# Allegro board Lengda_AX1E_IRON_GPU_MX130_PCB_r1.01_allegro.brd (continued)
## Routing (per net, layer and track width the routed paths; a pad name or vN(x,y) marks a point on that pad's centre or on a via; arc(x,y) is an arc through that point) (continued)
FRM_CLK: length 4.5
  TOP w0.102: U3.A3 28.11,37.82 28.11,34.02 R640.2
GC6_FB_EN: length 60.6
  TOP w0.102: v1(28.66,31.11) 28.78,31.22 28.78,34.46 28.51,34.73 28.51,36.62 29.28,37.4 U3.B2 ; v1(49.7,10.18) 50.03,9.84 GR8.2
  L3 w0.102: v1(29.3,10.51) 31.12,10.51 32.21,11.6 34.35,11.6 34.53,11.78 38.47,11.78 39.36,10.89 40.74,10.89 41.15,11.3 44.67,11.3 45.8,10.17 49.68,10.17 v1(49.7,10.18)
  L3 w0.127: v1(28.66,31.11) 28.66,30.19 27.13,28.66 27.13,18.27 28.83,16.57 v1(29.16,16.57)
  BOTTOM w0.102: R604.2 R603.1 29.64,30.78 29.31,31.11 v1(28.66,31.11) ; v1(29.16,16.57) 29.48,16.25 29.48,10.69 v1(29.3,10.51) 28.87,10.08 26.49,10.08 26.2,10.37 U44.2
GPIO0_PWM_VID: length 96.9
  TOP w0.102: v1(26.48,31.59) 27.35,32.46 27.36,39.77 27.52,39.93 28.83,39.93 29.18,40.28 29.82,40.28 30.08,40.54 U3.C6
  L3 w0.127: v1(67.02,45.24) 65.98,45.3 61.87,41.2 61.87,35.28 62.74,34.41 62.74,24.31 63.31,23.74 63.31,19.72 62.04,18.45 57.1,18.45 53.57,14.92 50.97,14.92 49.86,16.02 40.36,16.02 39.84,16.54 33.69,16.54 33.17,16.02 28.88,16.02 25.98,18.92 25.98,26.47 25.55,26.9 25.55,31.27 25.87,31.59 v1(26.48,31.59)
  BOTTOM w0.203: R651.1 66.9,45.9 67.02,45.78 v1(67.02,45.24)
GPIO2_GPU_EVENT_FBCLAMP: length 25.4
  TOP w0.102: U3.D6 31.28,41.09 v1(31.28,41.1)
  BOTTOM w0.102: Q36.2 24.58,23.85 24.09,24.34 R645.2 24.68,25.31 24.68,26.64 25.76,27.72 25.76,32.71 26.87,33.83 26.87,41.32 27.7,42.14 28.42,42.14 29.87,40.7 30.87,40.7 v1(31.28,41.1)
GPIO4_PWR_EN: length 108
  TOP w0.102: U3.F9 v1(32.13,42.78)
  L3 w0.102: v1(32.13,42.78) 32.55,42.35 32.55,37.17 31.81,36.43 31.81,34.14 32.55,33.41 32.55,32.04 28.89,28.38 28.89,24.97 28.31,24.39 v1(28.31,18.34) 29.15,18.34 30.24,17.25 55.4,17.25 56.85,18.7 61.89,18.7 63.09,19.91 63.09,23.5 62.51,24.08 62.51,34.11 61.37,35.25 61.37,41.34 67.46,47.44 v1(67.46,47.6) 67.16,47.91 61.42,47.91 v1(60.91,48.42)
  BOTTOM w0.102: U41.1 27.55,16.94 28.31,17.7 v1(28.31,18.34)
  BOTTOM w0.203: R736.2 R637.2 60.39,48.94 v1(60.91,48.42) ; R742.2 v1(67.46,47.6)
GPIO7_BL_PWM_GPU: length 11.8
  TOP w0.102: U3.B6 28.87,40.29 27.38,40.29 27.1,40.01 27.1,32.81 v1(26.47,32.17)
  BOTTOM w0.102: v1(26.47,32.17) 26.47,32.53 26.9,32.96 R635.2
GPIO8_MEM_VDD_CTL: length 3
  BOTTOM w0.127: R39.1 38.99,14.35 R40.1 R45.2 R37.2
GPIO8_MEM_VDD_CTL_R: length 47.1
  TOP w0.102: v1(31.29,43.58) 31.68,43.19 U3.E9
  L3 w0.102: v1(42.54,16.64) 42.15,17.04 29.96,17.04 29.31,17.68 28.42,17.68 27.9,18.2 27.9,27.82 32.27,32.19 32.27,33.3 31.51,34.07 31.51,36.66 31.78,36.92 31.78,39.24 31.67,39.34 31.67,43.02 31.29,43.4 v1(31.29,43.58)
  BOTTOM w0.127: v1(42.54,16.64) 42.54,14.48 42.28,14.22 R45.1
GPIO9_ALERT*: length 13.9
  TOP w0.102: U3.F8 v1(32.12,41.93)
  BOTTOM w0.102: v1(32.12,41.93) 32.12,41.19 31.37,40.44 29.78,40.44 28.33,41.89 27.79,41.89 27.22,41.32 27.22,35.66 R634.2
GPIO10_FBVREF_ALTV: length 63.5
  TOP w0.102: Q7.1 v1(13.77,87.22) ; U3.C5 30.43,39.5 v1(30.43,39.49)
  L3 w0.102: v1(13.77,87.22) 12.23,85.68 12.23,76.12 15.81,72.54 15.81,52.72 24.43,44.1 26.21,44.1 30.43,39.88 v1(30.43,39.49)
  BOTTOM w0.102: R638.2 28.37,35.28 28.37,36.33 29.68,37.64 R198.2 29.68,38.75 v1(30.43,39.49)
GPIO12_AC_DETECT_GPU: length 22.2
  TOP w0.102: U3.D7 v1(30.47,41.1)
  BOTTOM w0.102: v1(30.47,41.1) 29.79,41.1 28.49,42.4 27.58,42.4 26.54,41.36 26.54,33.86 25.5,32.82 25.5,28.68 23.99,27.17 R642.2 23.99,25.71 D9.P
GPIO13_BLEN_GPU: length 11.2
  TOP w0.102: v1(27.19,31.65) 27.57,32.03 27.57,39.26 27.75,39.44 28.84,39.44 U3.B4
  BOTTOM w0.102: v1(27.19,31.65) 26.92,31.38 R636.2
GPIO16_GPU_PEX_RST_MON: length 6.2
  TOP w0.102: U3.D5 v1(31.28,39.43)
  BOTTOM w0.102: R639.2 R34.1 30.48,35.34 30.48,38 30.89,38.41 30.89,38.75 31.28,39.14 v1(31.28,39.43)
GPIO17_MULTIPLE_USAGE: length 3.6
  TOP w0.102: U3.D4 30.88,39 v1(30.48,38.6)
  BOTTOM w0.102: R36.1 30.53,40.09 30.84,39.78 30.84,39.13 30.48,38.78 v1(30.48,38.6)
GPIO18_GM108_PEXRSTHOLD: length 13.4
  TOP w0.102: v1(25.1,27.65) 24.51,27.07 R35.1 ; v1(29.74,36.99) 29.74,37.06 U3.C2
  L3 w0.102: v1(25.1,27.65) 25.1,32.94 29.15,36.99 v1(29.74,36.99)
GPIO21_GPU_PEX_RST_HOLD: length 10.4
  TOP w0.102: R33.1 27.8,30.58 27.8,38.12 28.28,38.6 29.69,38.6 U3.C4
GPIO22_MEM_VDD_CTL2: length 45.2
  TOP w0.076: U3.A7 v1(28.02,41.5)
  L3 w0.102: v1(28.02,41.5) 28.02,40.22 31.28,36.96 31.28,33.91 32.05,33.14 32.05,32.35 27.56,27.86 27.56,18.23 28.71,17.07 29.54,17.07 29.81,16.81 40.27,16.81 v1(40.58,16.5)
  BOTTOM w0.102: v1(28.02,41.5) 28.02,40.33 R36.2
  BOTTOM w0.127: v1(40.58,16.5) 40.45,16.5 40.08,16.13 R41.2 R44.1 R43.1
GPIO23_GPU_PEX_RST_HOLD: length 17.9
  TOP w0.102: U3.B7 28.87,41.09 27.07,41.09 26.63,40.65 26.63,33.57 25.07,32.01 25.07,28.97 R35.2 23.43,27.34 R643.2
GPIO_NVVDD_PSI: length 90
  TOP w0.102: v1(28.03,39.01) 28.04,39 U3.A4
  L3 w0.127: v1(28.03,39.01) 28.03,36.35 24.45,32.77 24.45,26.57 25.65,25.37 25.65,18.76 28.68,15.74 37.95,15.74 38.21,16.01 40.02,16.01 40.28,15.74 49.05,15.74 50.34,14.45 53.77,14.45 57.48,18.15 62.17,18.15 63.55,19.54 63.55,23.95 62.98,24.52 62.98,34.71 62.34,35.35 62.34,39.53 64.91,42.09 v1(65.43,42.09)
  BOTTOM w0.203: v1(65.43,42.09) 65.13,41.79 R649.1
GPU_ADP_IN#: length 53.5
  TOP w0.102: v1(49.59,11.22) 49.47,11.22 49.25,11 GCN1.20
  L3 w0.102: v1(49.59,11.22) 49.57,11.22 49.09,11.7 42.93,11.7 41.85,12.78 37.96,12.78 37.59,12.41 33.69,12.41 33.46,12.18 31.57,12.18 30.71,11.32 27.8,11.32 25.27,13.85 25.27,15.02 23.48,16.81 23.48,23.88 22.64,24.72 21.84,24.72 21.46,24.34 v1(21.46,23.96)
  BOTTOM w0.102: v1(21.46,23.96) 21.46,25.13 22.03,25.7 D9.N
GPU_ALL_PWRGD_SOC: length 66
  L3 w0.102: v1(11.39,21.84) 12.48,20.75 12.48,9.49 17.17,4.81 39.2,4.81 40.12,3.89 48.65,3.89 50.14,5.38 55.27,5.38 57.66,2.99 v1(58.72,2.99)
  BOTTOM w0.127: v1(58.72,2.99) 58.45,2.72 GCN1.5
  BOTTOM w0.305: R757.2 C933.1 v1(11.39,21.84)
GPU_BUFRST*: length 1.9
  TOP w0.102: U3.D11 v1(30.5,44.38)
  BOTTOM w0.102: v1(30.5,44.38) 29.31,44.38 R587.2
GPU_EVENT: length 45.5
  TOP w0.127: GCN1.28 46.05,3.92 44.87,5.1 44.87,6.98 v1(44.88,6.99)
  L3 w0.127: v1(44.88,6.99) 44.09,6.99 43.4,7.69 25.39,7.69 19.66,13.42 v1(19.66,18.69)
  BOTTOM w0.127: R644.2 23.48,19.98 23.63,20.13 Q36.3 21.82,20.85 v1(19.66,18.69)
GPU_PEX_RST#: length 26.4
  TOP w0.102: GCN1.22 48.45,2.69 48.31,2.82 48.31,9.76
  TOP w0.127: 48.31,9.76 48.31,11.7 46.25,13.76 40.4,13.76 38.76,12.12 v1(38.76,12.02)
  BOTTOM w0.127: R31.1 35.93,11.61 36.34,12.02 U4.1 R30.2 v1(38.76,12.02)
GPU_PEX_RST_HOLD: length 27.3
  TOP w0.102: R33.2 26.72,30.62 v1(26.28,31.06)
  L6 w0.127: v1(37.8,11.37) 35.94,11.37 28.8,18.51 28.8,28.36 26.28,30.89 v1(26.28,31.06)
  BOTTOM w0.127: U4.2 v1(37.8,11.37)
GPU_PLLVDD: length 101.4
  L3 w0.406: v1(60.22,60.44) 60.91,59.76 60.91,58.64 61.85,57.7 61.85,55.56 57.62,51.33 57.62,48.67 60.03,46.26 60.03,38.78 59.06,37.8 59.06,36.73 61.9,33.89 61.9,29.05 54.75,21.9 54.75,20.1 53.99,19.33 36.16,19.33 34.67,20.82 34.67,26.83 35.79,27.95 35.79,33.94 36.22,34.37 v1(38.66,34.37) ; v1(32.91,46.08) 34.37,44.62 34.37,43.41 35.74,42.04 35.74,36.16 36.41,35.49 38.6,35.49 v1(38.96,35.12)
  BOTTOM w0.406: v1(32.91,46.08) 32.75,46.24 R259.1
GPU_PWR_EN: length 124.1
  TOP w0.102: v1(45.9,10.65) 45.77,10.53 GR11.2
  TOP w0.305: Q76.1 73.93,79.22 72.76,78.05 v1(72.38,78.05)
  L3 w0.102: v1(72.38,78.05) 71.45,77.12 71.45,76.02 68.57,73.13 68.57,65.91 v1(68.77,65.7) 68.77,63.61 71.87,60.51 71.87,45.99 66.4,40.52 66.4,35.84 64.53,33.98 64.53,27.81 65.76,26.57 65.76,23.87 64.66,22.76 64.66,18.08 63.56,16.99 63.56,11.63 62.59,10.65 v1(45.9,10.65) 45.05,11.5 42.75,11.5 41.74,12.5 38.18,12.5 37.71,12.03 34.14,12.03 33.95,11.84 31.71,11.84 30.77,10.9 27.43,10.9 24.87,13.47 v1(24.87,13.58)
  BOTTOM w0.102: v1(68.77,65.7) 68.77,65.6 68.49,65.32 R738.1 ; v1(24.87,13.58) 24.79,13.51 U43.2
  BOTTOM w0.254: R738.1 R737.2
I2C_CLK2_GPU: length 66.5
  TOP w0.127: v1(20.09,30.16) 19.91,29.98 19.91,26.62 20.03,26.51 20.03,23.86 20.96,22.93 22.78,22.93 23.5,23.64 U2.8 ; v1(44.3,12.53) 44.42,12.4 44.42,11.52 44.3,11.4 44.3,3.69 45.25,2.74 GCN1.30
  L3 w0.127: v1(20.09,30.16) 19.43,29.49 19.43,26.97 21.18,25.22 22.9,25.22 23.98,24.14 23.98,17.12 26.58,14.52 26.58,13.42 28.02,11.98 29.74,11.98 30.91,13.15 36.97,13.15 37.22,13.4 41.95,13.4 43.15,12.2 43.97,12.2 v1(44.3,12.53)
  BOTTOM w0.127: Q34.3 21.28,31.34 v1(20.09,30.16)
I2C_DATA2_GPU: length 66.5
  TOP w0.127: v1(43.46,12.6) 43.74,12.32 43.74,3.48 44.45,2.77 GCN1.32 ; v1(20.51,27.54) 20.42,27.45 20.42,27.17 20.53,27.06 20.99,27.06 21.13,26.92 21.13,26.67 21.02,26.55 20.69,26.55 20.56,26.42 20.56,26.17 20.69,26.04 21.2,26.04 21.32,25.92 21.32,25.66 21.2,25.54 20.69,25.54 20.56,25.41 20.56,25.15 20.69,25.03 21.3,25.03 21.42,24.9 21.42,24.65 21.3,24.52 20.69,24.52 20.56,24.39 20.56,24.14 21.16,23.54 22.47,23.54 23.22,24.29 U2.7
  L3 w0.127: v1(20.51,27.54) 20.57,27.6 20.57,28.69 20.41,28.86 20.08,28.86 19.94,28.72 19.94,27.23 20.5,26.68 20.51,26.68 21.4,25.79 23.2,25.79 24.56,24.43 24.56,17.28 27.44,14.4 27.44,13.41 28.28,12.57 29.44,12.57 30.59,13.72 36.8,13.72 37.01,13.92 42.43,13.92 42.62,13.73 42.8,13.73 43.25,14.17 43.43,14.17 43.61,13.99 43.61,13.81 43.16,13.37 43.16,13.19 43.46,12.9 v1(43.46,12.6)
  BOTTOM w0.127: v1(20.51,27.54) 19.96,27.54 19.67,27.83 19.67,28.5 19.91,28.75 Q35.3
I2CB_SCL_G: length 16.5
  TOP w0.102: v1(29.67,42.77) 29.67,42.79 U3.C9
  BOTTOM w0.102: v1(29.67,42.77) 29.53,42.91 27.27,42.91 25.82,41.46 25.82,34.07 25.03,33.28 25.03,31.1 R631.1
I2CB_SDA_G: length 14.4
  TOP w0.102: v1(30.48,42.76) U3.C8
  BOTTOM w0.102: v1(30.48,42.76) 30.05,43.19 27,43.19 25.43,41.61 25.43,34.95 R641.1
I2CC_SCL_G: length 16.6
  TOP w0.102: U3.A9 28.31,43.18 26.19,41.05 26.19,33.81 24.52,32.15 24.52,30.3 R619.1
I2CC_SDA_G: length 18
  TOP w0.102: R622.1 23.27,28.13 24.79,29.65 24.79,32.07 26.39,33.67 26.39,40.83 28.34,42.78 28.88,42.78 U3.B9
I2CS_SCL_G: length 16.7
  TOP w0.102: U3.D9 31.29,42.76 v1(31.29,42.75)
  BOTTOM w0.102: v1(31.29,42.75) 30.6,43.44 26.56,43.44 24.99,41.88 24.99,37.04 R614.2 23.08,34.81 23.31,34.58 Q34.2
I2CS_SDA_G: length 21
  TOP w0.102: U3.D8 v1(30.48,41.93)
  BOTTOM w0.102: v1(30.48,41.93) 30.07,42.33 29.31,42.33 29.02,42.63 27.39,42.63 26.19,41.42 26.19,34.03 25.26,33.1 25.26,29.42 R615.2 24.48,28.3 23.98,27.8 Q35.2
JTAG_TCLK: length 6
  TOP w0.102: TP9.1 48.65,35.83 48.65,39.3 48.28,39.67 U3.AE5
JTAG_TDI: length 2.8
  TOP w0.102: TP19.1 51.56,40.25 49.8,40.25 49.35,40.7 U3.AF6
JTAG_TDO: length 6.9
  TOP w0.102: TP24.1 46.19,35.85 46.19,38.35 46.42,38.58 46.77,38.58 47.07,38.87 47.07,40.26 47.48,40.68 U3.AD6
JTAG_TMS: length 4.1
  TOP w0.102: TP15.1 50.21,40.01 49.65,40.01 49.38,40.28 48.7,40.28 U3.AE6
JTAG_TRST*: length 3.9
  TOP w0.102: R605.1 TP26.1 49.88,38.76 U3.AG4
KBC_FAN_SPEED_GPU: length 121.8
  TOP w0.102: v1(59.27,3.96) 59.05,3.96 58.05,2.95 GCN1.6
  L3 w0.203: v1(59.27,3.96) 57.87,3.96 55.84,5.99 49.58,5.99 48.11,4.51 40.59,4.51 39.71,5.39 17.41,5.39 13.17,9.63 13.17,21.28 8.17,26.28 8.17,29.41 9.54,30.78 9.54,35.16 11.13,36.76 11.13,51.5 12,52.37 12,67.21 11.26,67.95 v1(11.26,70.68)
  BOTTOM w0.305: v1(11.26,70.68) 11.4,70.82 GR427.2 GC315.2 GQ2.3
NVVDD: length 3.5
  TOP w0.203: 68.69,43.95 69.11,43.95 69.11,43.53
  TOP w0.305: 68.81,43.66 69.35,44.2 R751.1
  BOTTOM w0.203: v1(68.76,31.93) 69.26,31.93 R677.2
  vias: v1(35.55,43.8) v1(35.66,49.76) v1(35.7,47.81) v1(35.68,45.68) v1(35.72,50.79) v1(36.27,37.01) v1(36.37,44.75) v1(36.33,38.65) v1(36.54,50.73) v1(36.54,48.76) v1(36.78,46.87) v1(36.74,42.18) v1(36.88,36.86) v1(36.89,34.94) v1(36.89,33.67) v1(36.94,36.05) v1(36.94,32.1) v1(36.94,30.9) v1(36.94,29.81) v1(36.94,28.71) v1(36.94,27.41) v1(37.05,41.1) v1(37.47,42.17) v1(37.66,49.63) v1(37.67,48.77) v1(37.69,43.8) v1(37.77,50.82) v1(37.85,45.84) v1(37.85,44.62) v1(38.7,49.81) v1(38.7,44.79) v1(38.68,43.79) v1(38.8,41.09) v1(39.19,42.22) v1(39.2,41.52) v1(39.45,50.8) v1(39.59,43.81) v1(39.52,41.1) v1(39.61,37) v1(39.68,49.58) v1(39.69,37.84) v1(40.45,41.06) v1(40.67,47.92) v1(40.69,46.87) v1(40.82,42.16) v1(41.26,41.05) v1(41.24,40.29) v1(41.54,42.16) v1(41.61,35.15) v1(41.64,49.75) v1(41.66,47.81) v1(41.72,44.72) v1(41.81,36.77) v1(41.82,36.14) v1(42.04,41.08) v1(42.1,40.23) v1(42.08,38.59) v1(42.11,37.89) v1(42.21,42.16) v1(42.13,39.35) v1(42.33,35.61) v1(42.32,34.96) v1(42.58,45.81) v1(42.68,48.8) v1(42.66,46.78) v1(42.62,43.88) v1(42.82,39.31) v1(42.88,38.6) v1(42.9,37.81) v1(42.86,36.15) v1(42.93,36.99) v2(38.98,32.39) v2(38.98,31.12) v2(38.98,29.85) v2(38.98,28.58) v2(38.98,27.31) v2(39.04,33.55) v2(40.46,33.64) v2(40.46,32.37) v2(40.46,31.1) v2(40.46,29.83) v2(40.46,28.56) v2(40.46,27.29) v2(41.99,33.61) v2(41.99,32.34) v2(41.99,31.07) v2(41.99,29.8) v2(41.99,28.53) v2(41.99,27.26) v2(43.43,33.64) v2(43.43,32.37) v2(43.43,31.1) v2(43.43,29.83) v2(43.43,28.56) v2(43.43,27.29) v2(44.79,33.64) v2(44.79,32.37) v2(44.79,31.1) v2(44.79,29.83) v2(44.79,28.56) v2(44.79,27.29) v2(56.2,44.52) v2(56.16,35.18) v2(56.16,34.32) v2(56.16,33.46) v2(56.12,32.59) v2(56.22,45.28) v2(56.29,31.84) v2(56.29,31.03) v2(56.29,30.18) v2(56.3,29.36) v2(56.35,28.57) v2(56.98,45.27) v2(56.98,44.51) v2(56.93,43.73) v2(56.93,42.88) v2(56.93,42.06) v2(56.92,41.23) v2(57,35.18) v2(57,34.32) v2(57,33.46) v2(56.96,32.59) v2(57.19,31.84) v2(57.16,31.04) v2(57.15,30.22) v2(57.12,29.44) v2(57.14,28.59) v2(57.81,34.28) v2(57.81,33.42) v2(57.77,32.56) v2(57.87,45.26) v2(57.87,44.47) v2(57.86,43.69) v2(57.86,42.84) v2(57.86,42.02) v2(57.86,41.23) v2(58.01,31.6) v2(58.57,33.39) v2(58.6,32.52) v2(58.8,31.54)
NVVDD_GND_SENSE: length 91.2
  TOP w0.101: U3.F1 32.48,36.5 v1(32.48,34.88)
  L3 w0.203: v1(61.84,20.9) 61.99,21.05 62.31,21.05 62.48,20.87 62.48,20.45 61.84,19.8 56.54,19.8 55.25,18.51 35.48,18.51 34,20 34,28.58 33.46,29.11 33.46,34.14 32.73,34.88 v1(32.48,34.88)
  L6 w0.203: v1(68.17,45.12) 69.19,44.1 69.19,40.61 v1(69.61,40.19) 69.61,35.36 v1(68.99,34.74) 68.99,33.3 70.42,31.87 71.04,31.87 71.7,31.21 71.7,26.05 68.92,23.27 65.54,23.27 63.31,21.04 61.98,21.04 v1(61.84,20.9)
  BOTTOM w0.203: C890.2 v1(68.17,45.12) ; GU1.10 65.84,38.11 67.3,36.65 68.51,36.65 68.99,36.17 v1(68.99,34.74) R665.1 69.13,34.18 69.91,33.4 C893.1
  BOTTOM w0.305: R658.2 69.19,40.61 v1(69.61,40.19)
NVVDD_SENSE: length 75.3
  TOP w0.101: 32.05,34.41 32.05,35.05 31.97,35.13 31.87,35.13 31.77,35.23 31.77,35.4 31.87,35.5 32.1,35.5 32.2,35.6 32.2,35.77 32.1,35.87 31.87,35.87 31.77,35.97 31.77,36.13 31.87,36.24 32.1,36.24 32.2,36.34 32.2,36.8 32.58,37.19 U3.F2
  TOP w0.102: 32.05,34.41 32.13,34.32 v1(32.48,34.32)
  L3 w0.203: v1(61.85,21.51) 61.98,21.38 62.46,21.38 62.79,21.05 62.79,20.26 61.96,19.44 56.64,19.44 55.41,18.2 35.31,18.2 33.68,19.83 33.68,28.26 33.13,28.81 33.13,33.86 32.67,34.32 v1(32.48,34.32)
  L6 w0.203: v1(61.85,21.51) 61.98,21.38 63.14,21.38 65.41,23.64 68.68,23.64 71.35,26.31 71.35,31.04 70.89,31.5 70.22,31.5 69.11,32.61 v1(68.41,32.61)
  BOTTOM w0.203: C892.2 R676.2 C893.2 R677.1 v1(68.41,32.61)
OVERT: length 5.4
  TOP w0.102: GCN1.46 38.85,4.69 38.31,5.23 Q33.3
OVERT1: length 31.1
  TOP w0.127: v1(36.25,14.25) 36.25,13.92 36.21,13.89 C867.2 37.04,9.69 37.36,9.37 Q33.2 ; R618.1 22.01,25.76 21.51,26.26 v1(21.51,26.36)
  L3 w0.127: v1(36.25,14.25) 35.92,14.59 27.97,14.59 24.97,17.58 24.97,24.81 23.42,26.36 v1(21.51,26.36)
PCIE_RXN1_GPU: length 5
  TOP w0.109: GCN1.44 39.65,2.6 39.84,2.79 39.84,3.41 40.69,4.26 40.69,5.6 C331.1
PCIE_RXN2_GPU: length 4.7
  TOP w0.109: GCN1.38 42.05,2.61 42.24,2.8 42.24,5.66 C333.1
PCIE_RXN3_GPU: length 4.7
  BOTTOM w0.127: GCN1.51 36.85,2.68 37.14,2.97 37.14,5.61 C532.1
PCIE_RXN4_GPU: length 4.7
  BOTTOM w0.127: C534.1 39.55,5.43 39.55,2.89 39.25,2.59 GCN1.45
PCIE_RXP1_GPU: length 5.1
  TOP w0.109: C330.1 40.91,5.58 40.91,4.17 40.06,3.32 40.06,2.95 40.45,2.56 GCN1.42
PCIE_RXP2_GPU: length 4.8
  TOP w0.109: C332.1 42.46,5.56 42.46,2.78 42.85,2.39 GCN1.36
PCIE_RXP3_GPU: length 4.7
  BOTTOM w0.127: C478.1 37.38,5.55 37.38,2.95 37.65,2.68 GCN1.49
PCIE_RXP4_GPU: length 4.6
  BOTTOM w0.127: C533.1 39.79,5.6 39.79,2.74 40.05,2.47 GCN1.43
PCIE_TXN1_GPU: length 49.5
  TOP w0.109: U3.AG7 50.19,41.19 52.13,41.19 52.72,40.6 52.72,32.44 51.41,31.13 51.41,22.18 51.55,22.04 51.79,22.04 v1(51.97,22.22)
  BOTTOM w0.109: GCN1.39 41.65,2.47 41.93,2.75 41.93,3.53 44.78,6.37 47.06,6.37 50.91,10.22 50.91,21.57 51.41,22.07 51.81,22.07 v1(51.97,22.22)
PCIE_TXN2_GPU: length 51.8
  TOP w0.109: U3.AE7 48.41,41.62 48.67,41.62 48.91,41.86 49.35,41.86 49.56,42.08 50.25,42.08 50.4,41.93 52.62,41.93 53.47,41.08 53.47,32.08 52.74,31.36 52.74,22.15 52.98,21.91 53.23,21.91 v1(53.44,22.12)
  BOTTOM w0.109: v1(53.44,22.12) 53.26,21.94 52.89,21.94 52.51,21.57 52.51,10.73 47.43,5.65 45.64,5.65 44.05,4.06 GCN1.33
PCIE_TXN3_GPU: length 50.5
  TOP w0.109: v1(53.42,23.4) 53.66,23.64 53.94,23.64 54.18,23.88 54.18,41.67 53.07,42.78 51.84,42.78 51.48,42.78 51.24,43.02 50.34,43.02 50.16,42.83 49.43,42.83 U3.AF9
  BOTTOM w0.109: GCN1.25 47.25,2.79 47.32,2.86 47.7,2.86 47.83,2.99 47.83,4.97 54.05,11.18 54.05,23.41 53.87,23.59 53.61,23.59 v1(53.42,23.4)
PCIE_TXN4_GPU: length 50
  TOP w0.109: U3.AG10 50.18,43.68 52.96,43.68 52.96,43.68 53.69,43.68 54.93,42.44 54.93,20.95 55.15,20.73 55.3,20.73 v1(55.48,20.91)
  BOTTOM w0.109: GCN1.19 49.65,1.89 49.64,1.9 49.64,5.62 54.8,10.77 54.8,20.45 55.07,20.72 55.29,20.72 v1(55.48,20.91)
PCIE_TXP1_GPU: length 49.5
  TOP w0.109: v1(51.97,21.65) 51.79,21.83 51.46,21.83 51.19,22.09 51.19,31.22 52.5,32.53 52.5,40.51 52.03,40.97 50.16,40.97 U3.AG6
  BOTTOM w0.109: v1(51.97,21.65) 51.77,21.85 51.5,21.85 51.13,21.48 51.13,10.13 47.16,6.15 44.87,6.15 43,4.28 43,4.13 43.07,4.06 43.07,3.93 42.92,3.77 42.74,3.77 42.69,3.82 42.54,3.82 42.15,3.43 42.15,2.76 42.45,2.46 GCN1.37
PCIE_TXP2_GPU: length 51.8
  TOP w0.109: U3.AF7 49.23,41.65 49.44,41.65 49.65,41.86 50.16,41.86 50.31,41.71 52.53,41.71 53.25,40.99 53.25,32.17 52.52,31.45 52.52,22.06 52.89,21.69 53.29,21.69 v1(53.44,21.54)
  BOTTOM w0.109: GCN1.31 44.85,2.73 44.76,2.82 44.41,2.82 44.27,2.97 44.27,3.96 44.7,4.4 44.86,4.4 45.09,4.16 45.24,4.16 45.4,4.32 45.4,4.47 45.17,4.71 45.17,4.86 45.73,5.43 47.52,5.43 52.73,10.64 52.73,21.48 52.98,21.72 53.26,21.72 v1(53.44,21.54)
PCIE_TXP3_GPU: length 50.5
  TOP w0.109: v1(53.42,23.98) 53.53,23.86 53.85,23.86 53.96,23.97 53.96,41.58 52.97,42.56 51.84,42.56 51.66,42.56 51.39,42.56 51.15,42.8 50.43,42.8 50.25,42.61 49.34,42.61 49.14,42.81 48.93,42.81 48.56,43.18 U3.AE9
  BOTTOM w0.109: v1(53.42,23.98) 53.58,23.81 53.96,23.81 54.27,23.51 54.27,11.09 48.05,4.88 GCN1.23
PCIE_TXP4_GPU: length 50
  TOP w0.109: U3.AG9 50.17,43.46 52.96,43.46 52.96,43.46 53.6,43.46 54.71,42.35 54.71,20.86 55.06,20.51 55.3,20.51 v1(55.48,20.33)
  BOTTOM w0.109: v1(55.48,20.33) 55.31,20.5 55.16,20.5 55.02,20.36 55.02,10.68 49.86,5.53 49.86,3 49.99,2.87 50.22,2.87 50.45,2.64 GCN1.17
PEX_CLKREQ_GPU#: length 57.4
  TOP w0.102: U3.AC6 46.69,40.7 v1(47.08,41.09)
  L3 w0.102: v1(62.1,11.69) 61.44,12.35 45.47,12.35 44.91,12.91 44.91,13.32 v1(44.92,13.33)
  BOTTOM w0.102: R153.1 60.2,6.76 Q6.2 R100.2 62.33,10.78 62.1,11 v1(62.1,11.69) ; v1(44.92,13.33) 44.92,21.2 50.27,26.55 50.27,37.9 v1(47.08,41.09)
PEX_PLL_CLK_OUT: length 1.3
  TOP w0.102: v1(48.69,53.5) U3.AF22
  BOTTOM w0.102: v1(48.69,53.5) 48.82,53.36 R12.1
PEX_PLL_HVDD: length 1.9
  TOP w0.203: v1(44.41,42.26) 44.49,42.34 U3.AA8 44.98,43.12 U3.AA9 45.04,43.19 v1(44.74,43.49)
PEX_RST#: length 57.8
  TOP w0.102: U3.AC7 v1(47.07,41.92)
  TOP w0.127: v1(45.52,13.02) 45.26,12.77 44.81,12.77 44.39,13.19 40.68,13.19 39.26,11.77 Q33.1
  BOTTOM w0.102: v1(45.52,13.02) 45.52,21.33 50.55,26.36 50.55,38.11 47.54,41.13 47.54,41.46 v1(47.07,41.92)
  BOTTOM w0.127: R32.1 U4.4 R31.2 34.98,9.55 35.38,9.15 36.97,9.15 40.86,13.04 44.55,13.04 44.78,12.81 45.25,12.81 45.47,13.02 v1(45.52,13.02)
PEX_SVDD_3V3: length 1.7
  TOP w0.305: U3.AB8 v1(45.43,41.95)
  BOTTOM w0.203: R8.2 46.01,41.36 v1(45.43,41.95)
PEX_TERMP: length 2.5
  TOP w0.111: U3.AF25 49.09,56.4 v1(49.48,56.79)
  BOTTOM w0.203: v1(49.48,56.79) 49.48,56.96 50.23,57.71 R171.2
PEX_TX0: length 52.7
  TOP w0.109: U3.AC9 v1(46.24,42.76) ; v1(41.09,12.05) 40.91,11.87 40.91,7.11 C330.2
  BOTTOM w0.109: v1(46.24,42.76) 45.97,42.76 45.89,42.84 45.89,43.05 46.01,43.17 48.12,43.17 48.49,42.8 48.7,42.8 48.81,42.7 48.81,42.51 48.92,42.4 49.14,42.4 49.25,42.51 49.25,42.7 49.36,42.8 49.58,42.8 49.69,42.7 49.69,42.51 49.8,42.4 50.02,42.4 50.13,42.51 50.13,42.7 50.24,42.8 50.95,42.8 52.12,41.64 52.12,27.14 46.58,21.6 46.58,13.25 44.59,11.26 41.04,11.26 40.86,11.44 40.86,11.82 v1(41.09,12.05)
PEX_TX0#: length 52.8
  TOP w0.109: v1(40.51,12.05) 40.69,11.87 40.69,7.09 C331.2 ; U3.AB9 v1(45.44,42.78)
  BOTTOM w0.109: v1(40.51,12.05) 40.64,11.91 40.64,11.35 40.95,11.04 44.68,11.04 46.8,13.16 46.8,21.51 52.34,27.05 52.34,41.73 51.04,43.02 48.58,43.02 48.21,43.39 45.92,43.39 45.67,43.14 45.67,42.86 45.59,42.78 v1(45.44,42.78)
PEX_TX1: length 51.8
  TOP w0.109: U3.AB10 45.44,44.38 v1(45.44,44.41) ; v1(42.69,10.39) 42.51,10.21 42.51,7.12 C332.2
  BOTTOM w0.109: v1(42.69,10.39) 42.46,10.17 42.46,9.94 42.64,9.76 44.09,9.76 47.6,13.27 47.6,21.56 52.87,26.83 52.87,42.39 51.58,43.68 51.38,43.68 51.22,43.52 50.94,43.52 50.78,43.68 50.5,43.68 50.34,43.52 50.07,43.52 49.91,43.68 49.63,43.68 49.47,43.52 49.19,43.52 49.03,43.68 46.05,43.68 45.83,43.89 45.83,44.32 45.74,44.41 v1(45.44,44.41)
PEX_TX1#: length 51.9
  TOP w0.109: U3.AC10 46.68,43.99 v1(46.26,44.41) ; C333.2 42.29,7.11 42.29,10.22 v1(42.11,10.39)
  BOTTOM w0.109: v1(46.26,44.41) 46.11,44.41 46.05,44.35 46.05,43.98 46.14,43.89 51.67,43.89 53.09,42.48 53.09,26.74 47.82,21.47 47.82,13.18 44.18,9.54 42.54,9.54 42.24,9.85 42.24,10.26 v1(42.11,10.39)
PEX_TX2: length 55
  TOP w0.109: U3.AD11 v1(47.08,45.23)
  BOTTOM w0.109: v1(47.08,45.23) 47.51,44.8 52.02,44.8 53.8,43.02 53.8,26.43 49,21.63 49,12.86 44.92,8.78 38.65,8.78 37.4,7.54 37.4,7.1 C478.2
PEX_TX2#: length 55
  TOP w0.109: U3.AC11 46.68,44.81 v1(47.08,44.41)
  BOTTOM w0.109: v1(47.08,44.41) 47.26,44.58 47.69,44.58 47.88,44.39 48.13,44.39 48.32,44.58 48.57,44.58 48.76,44.39 49,44.39 49.2,44.58 49.44,44.58 49.63,44.39 49.88,44.39 50.07,44.58 51.93,44.58 53.58,42.93 53.58,26.52 48.78,21.72 48.78,12.95 44.83,9 38.56,9 37.19,7.63 37.19,7.12 C532.2
PEX_TX3: length 55.9
  TOP w0.109: U3.AC12 v1(46.27,46.07)
  BOTTOM w0.109: v1(46.27,46.07) 46.48,45.86 52.28,45.86 54.52,43.61 54.52,26.13 50.02,21.63 50.02,12.75 45.06,7.79 40.12,7.79 39.7,7.37 39.7,7.02 C533.2
PEX_TX3#: length 55.8
  TOP w0.109: U3.AB12 46.26,45.24 v1(46.26,45.23)
  BOTTOM w0.109: C534.2 39.48,7.04 39.48,7.46 40.03,8.01 44.97,8.01 49.8,12.84 49.8,21.72 54.31,26.22 54.31,43.52 52.18,45.64 46.39,45.64 46.26,45.51 v1(46.26,45.23)
PEX_VDD: length 28.4
  TOP w0.305: C926.1 72.92,73.99 R746.1 72.92,72.53 73.6,71.86 73.6,69.13 71.81,67.34 68.83,67.34 65.06,63.57 65.06,60.74 64.39,60.06 61.28,60.06 60.86,59.64 60.86,58.76 60.65,58.55 C923.1
  TOP w0.406: 54.13,57.56 53.75,57.94 ; 54.13,57.56 54.13,57.97 ; 54.13,57.56 R752.1 ; 54.13,57.56 54.46,57.89
  vias: v1(44.54,53.54) v1(45.39,54.4) v1(46.22,55.2) v1(47.07,56.02) v1(47.88,57.6) v1(47.88,56.8) v3(51.37,58.72) v3(52.07,58.72) v3(52.81,58.72) v3(53.56,58.72) v3(54.34,58.72) v3(55.21,58.72) v3(55.84,59.38) v3(56.29,59.7) v3(56.29,59.06) v3(56.79,59.7) v3(56.79,59.07) v3(58.17,49.57) v3(58.17,49.04) v3(58.67,49.57) v3(58.67,49.04)
PS1_NVVDD_BOOT1: length 1.7
  BOTTOM w0.203: GU1.1 62.11,40.67 61.67,41.1
  BOTTOM w0.406: 61.67,41.1 R646.2
PS1_NVVDD_BOOT1_RC: length 1
  BOTTOM w0.508: R646.1 C877.1
PS1_NVVDD_BOOT2: length 1.6
  BOTTOM w0.203: GU1.18 62.11,35.93
  BOTTOM w0.406: 62.11,35.93 61.51,35.33 R652.2
PS1_NVVDD_BOOT2_RC: length 1
  BOTTOM w0.508: R652.1 C880.1
PS1_NVVDD_EN: length 6.4
  BOTTOM w0.203: R743.2 R744.2 64.48,45 63.93,44.46 C878.2 63.64,44.19 63.39,43.94 63.39,41.65 63.11,41.36 GU1.3
PS1_NVVDD_FB: length 3.4
  BOTTOM w0.203: R670.1 R666.1 65.91,37.61 GU1.11
PS1_NVVDD_FB_RC: length 0.9
  BOTTOM w0.203: C892.1 R666.2
PS1_NVVDD_LG1: length 25.7
  TOP w0.508: Q38.4 73.53,49.7 73.01,50.22 v1(70.04,50.22)
  L3 w0.635: v1(70.04,50.22) v1(66.51,50.22) 63.79,50.22 v2(62.42,48.85)
  BOTTOM w0.203: GU1.23 60.5,39.11 59.99,39.62
  BOTTOM w0.508: Q39.4 v1(66.51,50.22)
  BOTTOM w0.635: v2(62.42,48.85) 59.4,45.83 R650.1 59.99,39.62
PS1_NVVDD_LG2: length 19
  TOP w0.508: Q41.4 69.74,27.16 v2(69.76,27.15)
  L6 w0.635: v2(69.76,27.15) 68.85,27.15 60.55,35.44 v2(59.33,35.44)
  BOTTOM w0.305: R659.1 59.75,36.21 60.25,36.71 60.25,37.25 60.6,37.61 GU1.20
  BOTTOM w0.508: Q42.4 v2(69.76,27.15)
  BOTTOM w0.635: R659.1 59.34,35.44 v2(59.33,35.44)
PS1_NVVDD_PGOOD: length 66.2
  L3 w0.203: v1(63.25,35.32) 63.25,24.82 63.84,24.22 63.84,19.07 62.59,17.81 57.85,17.81 53.78,13.75 49.94,13.75 48.29,15.4 40.21,15.4 39.97,15.64 38.27,15.64 38.02,15.4 28.37,15.4 v1(27.5,16.27)
  BOTTOM w0.203: R749.2 27.6,10.96 U44.1 26.76,11.05 26.76,11.69 26.3,12.15 26.3,13.9 R756.1 27.36,14.96 27.36,16.13 v1(27.5,16.27) 27.48,16.29 U41.2 ; GU1.16 63.11,35.46 v1(63.25,35.32)
PS1_NVVDD_PH1_Q: length 27.7
  L3 w0.305: v2(66.62,56) 64.17,53.55 64.17,52.53 60.31,48.67 60.31,47.94 v1(62.22,46.03)
  BOTTOM w0.203: 60.68,40.09 61.16,39.61 GU1.24
  BOTTOM w0.406: v1(62.22,46.03) 61.67,45.49 C877.2
  BOTTOM w0.635: 60.68,40.09 60.68,45.59 63.87,48.77 v2(63.87,51.33)
  vias: v2(67.4,56.03) v2(68.17,56.03) v2(68.99,56.04)
PS1_NVVDD_PH2_Q: length 23.9
  TOP w0.406: 72.4,21.56 72.4,21.17 ; 72.4,21.17 72.19,21.38 ; 72.4,21.17 71.91,21.17 ; 72.4,21.17 72.57,21 C889.1
  L6 w0.406: v2(64.48,25.6) 63.83,26.24 63.83,28.38 v1(60.56,31.66)
  L6 w0.635: v2(65.15,25.96) 65.15,28.67 v2(60.56,33.27)
  BOTTOM w0.305: GU1.19 61.36,36.67
  BOTTOM w0.406: C880.2 v1(60.56,31.66)
  BOTTOM w0.508: 61.36,36.67 60.56,35.87
  BOTTOM w0.635: 60.56,35.87 v2(60.56,33.27)
  vias: v2(65.13,25.2) v2(67.87,21.66) v2(69.11,21.66) v2(70.38,21.65)
PS1_NVVDD_PSI: length 3.2
  BOTTOM w0.203: R648.2 63.94,42.6 R647.2 R649.2 63.95,41.4 63.61,41.06 GU1.4
PS1_NVVDD_REFADJ: length 5.2
  BOTTOM w0.203: R656.1 67.19,43.55 66.95,43.31 66.95,42.3 66.47,41.81 66.47,41.39 65.44,40.36 GU1.6
PS1_NVVDD_REFIN: length 4.1
  BOTTOM w0.203: R654.2 66.88,41.48 66.88,40.33 R657.1 66.14,39.99 65.75,39.61 GU1.7
PS1_NVVDD_SENSE_R: length 0.9
  BOTTOM w0.203: R676.1 R670.2
PS1_NVVDD_UG1: length 26.6
  TOP w0.508: Q37.4 73.55,56.83 73.11,57.26 v1(70.17,57.26)
  BOTTOM w0.203: GU1.2 62.61,41.57 62.71,41.67
  BOTTOM w0.508: 62.71,41.67 62.71,43.74
  BOTTOM w0.635: v1(70.17,57.26) 69.95,57.47 66.42,57.47 64.94,55.99 64.94,47.67 62.71,45.45 62.71,43.74
PS1_NVVDD_UG2: length 18.7
  TOP w0.508: Q40.4 66.1,20.88 v2(65.96,20.74)
  BOTTOM w0.203: 62.53,35.15 62.61,35.22 GU1.17
  BOTTOM w0.508: 62.53,34.47 62.53,35.15
  BOTTOM w0.635: v2(65.96,20.74) 64.44,20.74 63.23,21.95 63.23,31.23 62.53,31.93 62.53,34.47
PS1_NVVDD_VREF: length 14.8
  L6 w0.203: v1(66.03,32.72) 69.01,35.69 v1(69.01,39.9)
  BOTTOM w0.203: GR6.1 65.45,33.87 66.03,33.29 v1(66.03,32.72) ; v1(69.01,39.9) 69.01,39.33 R655.1 68.31,38.63 67.12,38.63 C879.2 66.5,39.11 GU1.8
PS2_FBVDD_PGOOD: length 6.9
  BOTTOM w0.305: U46.2 9.79,27.54 8.8,28.53 8.8,31.58 9.02,31.79 R700.1
PS2_FBVDDQ_EN: length 22.1
  L3 w0.305: v1(24.83,14.75) 22.83,16.74 22.83,18.9 20.46,21.28 20.46,25.02 18.33,27.16 18.33,30.87 v1(18.25,30.94)
  BOTTOM w0.305: U44.4 25.55,14.08 R756.2 24.88,14.75 v1(24.83,14.75)
  BOTTOM w0.406: R687.1 v1(18.25,30.94)
PS5_1V05_PGOOD: length 145.4
  TOP w0.203: U40.9 69.78,69.91 R740.2 70.29,69.91 v1(70.29,69.91)
  L3 w0.305: v1(9.14,27.2) 9.14,27.01 14.95,21.2 14.95,13.89 14.12,13.06 14.12,10.58 18.34,6.37 40.47,6.37 41.29,5.56 47.27,5.56 48.65,6.94 57.43,6.94 58.39,5.97 59.97,5.97 60.4,6.41 62.92,6.41 66.2,9.69 66.2,15.47 72.7,21.97 72.7,41.85 73.47,42.61 73.47,61.24 72.12,62.59 72.12,63.54 73.84,65.26 73.84,67.75 71.68,69.91 v1(70.29,69.91)
  BOTTOM w0.305: U46.1 v1(9.14,27.2)
PS5_PEXVDD_EN: length 110
  TOP w0.102: v1(71.55,67.93) 71.7,68.07 R745.1
  L3 w0.102: v1(23.6,11.96) 23.6,11.49 25.26,9.82 25.3,9.82 25.86,9.26 31.23,9.26 32.66,10.7 37.08,10.7 38.29,9.49 44.57,9.49 44.88,9.17 61.81,9.17 63.91,11.27 63.91,16.82 64.86,17.77 64.86,22.55 66.32,24.01 66.32,26.62 64.83,28.11 64.83,33.88 66.62,35.67 66.62,40.33 72.12,45.83 72.12,60.64 69.84,62.92 69.84,66.43 71.34,67.93 v1(71.55,67.93)
  BOTTOM w0.102: v1(23.6,11.96) 23.6,12.12 22.86,12.86 U43.4
PS_FBVDD_SEL: length 2.3
  BOTTOM w0.127: R39.2 C22.2 37.12,15.4 Q4.1
PS_FBVDD_SEL2: length 2
  BOTTOM w0.127: R43.2 C23.2 Q2.1
PS_FBVDD_SEL2_Q: length 2.1
  BOTTOM w0.127: Q2.3 R42.1
PS_FBVDD_SEL_Q: length 2.5
  BOTTOM w0.127: R38.1 32.96,14.92 Q4.3
ROM_CS*: length 36.3
  TOP w0.102: U3.D12 v1(31.28,45.23)
  L3 w0.102: v1(19.58,43.72) 16.83,40.97 16.83,34.19 15.43,32.78 15.43,27.45 13.77,25.79 v1(13.77,24.16)
  BOTTOM w0.102: v1(31.28,45.23) 30.89,45.62 25.93,45.62 24.76,44.46 20.32,44.46 v1(19.58,43.72)
  BOTTOM w0.127: v1(13.77,24.16) 13.77,24.13 R483.1
ROM_CS_R*: length 2.3
  BOTTOM w0.127: U36.1 R483.2 R480.1
ROM_SCLK: length 46.9
  TOP w0.111: U3.C12 29.89,45.66 29.48,45.25 29.13,45.25 28.84,44.96 26.44,44.96 24.54,43.06 21.97,43.06 v1(21.37,43.66)
  L3 w0.102: v1(21.37,43.66) 20.69,42.97 19.58,42.97 17.6,40.99 17.6,33.55 16.52,32.47 16.52,13.11 v1(15.49,12.08)
  BOTTOM w0.127: v1(15.49,12.08) R592.1 R597.2 R517.1
ROM_SCLK_R: length 1.6
  BOTTOM w0.127: R517.2 17,13.74 U36.6
ROM_SI: length 47.5
  TOP w0.111: U3.B12 29.13,45.66 28.69,45.22 26.25,45.22 24.35,43.31 22.54,43.31 v1(22.15,43.71)
  L3 w0.102: v1(19.81,12.08) 17.73,12.08 16.9,12.91 16.9,32.37 17.87,33.33 17.87,40.84 19.71,42.68 21.12,42.68 v1(22.15,43.71)
  BOTTOM w0.127: R516.1 R595.2 R588.1 v1(19.81,12.08)
ROM_SI_R: length 1.6
  BOTTOM w0.127: U36.5 18.27,13.69 R516.2
ROM_SO: length 34.3
  TOP w0.111: U3.A12 26.13,45.66 24.6,44.13 20.7,44.13 v1(20.32,43.74)
  L3 w0.102: v1(20.32,43.74) 19.88,43.3 19.48,43.3 17.25,41.07 17.25,33.97 15.79,32.5 15.79,27.95 15.79,27.26 14.22,25.69 14.22,24.32 v1(14.35,24.19)
  BOTTOM w0.127: U36.2 R596.2 R589.1 14.52,24.02 v1(14.35,24.19)
SP_PLLVDD: length 1.2
  TOP w0.305: U3.M6 37.14,40.22 v1(37.14,40.22) U3.L6
STRAP0: length 8.3
  TOP w0.102: R485.1 R528.2 29.74,30.88 29.74,35.36 30.88,36.5 U3.D1
STRAP1: length 7.6
  TOP w0.102: U3.D2 31.25,37.03 31.25,36.42 30.06,35.23 30.06,32.16 R486.1 R532.2
STRAP2: length 8.3
  TOP w0.102: U3.E4 v1(31.31,38.58)
  BOTTOM w0.102: v1(31.31,38.58) 31.31,38.43 30.86,37.98 30.86,35.49 31.23,35.12 31.23,33.57 31,33.35 R505.1 R533.2
STRAP3: length 6.8
  TOP w0.102: R507.1 R556.2 30.39,33.78 30.39,35.21 31.6,36.42 31.6,36.65 32.14,37.19 32.14,37.79 U3.E3
STRAP4: length 12.6
  TOP w0.102: R566.2 R514.1 28.28,28.07 28.57,28.36 28.57,29.71 29.43,30.56 29.43,35.41 30.51,36.49 30.51,37.82 U3.D3
STRAP5: length 8.9
  TOP w0.102: R515.1 R570.2 27.87,29.64 29.13,30.9 29.13,35.65 U3.C1
STRAP_VDD0: length 40.9
  TOP w0.305: R507.2 32.49,32.38 33.03,31.83 33.03,29.98 32.2,29.15 R485.2 ; R507.2 R486.2 ; R507.2 31.64,32.83 v1(31.61,32.86) ; R514.2 R515.2 v1(26.19,28.86)
  L3 w0.305: v1(31.61,32.86) 29.63,32.86 27.06,30.3 27.06,29.74 v1(26.19,28.86)
  L6 w0.305: v1(18.89,11.14) 18.39,11.64 18.39,19.72 18.89,20.22 18.89,25.07 19.52,25.7 22.16,25.7 25.33,28.86 v1(26.19,28.86)
  BOTTOM w0.305: v1(31.61,32.86) 31.95,32.52 R505.2 ; v1(18.89,11.14) R598.2 R599.2
STRAP_VDD1: length 19.7
  L3 w0.305: v1(15.24,11.36) 14.97,11.63 14.97,12.62 15.93,13.57 15.93,24.04 14.91,25.05 v1(14.91,25.65)
  BOTTOM w0.305: R588.2 R592.2 16.66,11.68 R594.2 R593.2 15.46,11.14 v1(15.24,11.36) ; R589.2 v1(14.91,25.65)
SYS_PEX_RST_MON#: length 28
  L6 w0.127: v1(30.82,34.09) 29.67,32.94 29.67,23.74 29.13,23.21 29.13,18.81 34.98,12.97 v1(37.52,12.97)
  BOTTOM w0.102: R34.2 v1(30.82,34.09)
  BOTTOM w0.127: R30.1 v1(37.52,12.97)
VID_PLLVDD: length 6.5
  TOP w0.305: v1(38.78,40.2) U3.N6
  BOTTOM w0.508: R482.2 40.85,39.59 40.07,40.37 C866.1 38.96,40.37 v1(38.78,40.2)
XTAL_SSFOUT: length 22.1
  TOP w0.102: R28.1 R29.2 18.57,30.2 19.48,31.12 22.63,31.12 R391.2 23.39,30.63 23.91,31.16 23.91,32.24 25.67,33.99 25.67,41.31
  TOP w0.111: 25.67,41.31 28.34,43.98 U3.A10
XTALIN: length 19.1
  TOP w0.102: X6.1 21.27,33.76 22.54,33.76 22.89,34.11 C864.1 23.63,34.11 24.73,35.21 24.73,41.98 27.38,44.63 28.93,44.63 29.13,44.43 29.7,44.43 U3.C11
XTALOUT: length 16.5
  TOP w0.102: X6.3 22.27,33.24 C865.1 23.27,33.24 24.98,34.96 24.98,41.84 27.51,44.37 28.81,44.37 29.2,43.98 U3.B10
XTALOUTB: length 20.7
  TOP w0.102: 25.95,41.24 25.95,33.89 24.18,32.12 24.18,30.57 23.32,29.72 R392.1 23.04,29.72 22.57,30.19 20.94,30.19 R257.1
  TOP w0.111: 25.95,41.24 28.3,43.6 29.7,43.6 30.08,43.98 U3.C10
N37829238:
  vias: v1(44.68,44.79) v1(45.01,49.51) v1(45.27,50.05) v1(45.44,51.86) v1(45.45,46.07) v1(46.26,49.35) v1(46.24,48.54) v1(47.1,49.35) v3(47.08,47.72) v3(47.9,50.2) v3(48.7,50.21) v3(49.5,51.82) v3(50.46,52.34) v3(50.53,51.8) v3(51.02,52.35) v3(51.54,52.35)
N37838176: length 1.7
  TOP w0.127: C541.1 26.11,68.04 R177.1 26.98,68.05 R176.2
N37838335: length 9.2
  TOP w0.305: M1.J10 26.01,78.54 v1(26.67,78.53)
  L3 w0.305: v1(27.67,86.05) 27.14,85.51 27.14,78.96 26.71,78.53 v1(26.67,78.53)
  BOTTOM w0.305: R187.2 v1(27.67,86.05)
N37838338: length 1.8
  TOP w0.305: v1(34.09,78.55) 33.92,78.55 33.91,78.55 M1.J1
  BOTTOM w0.127: R1722.2 34.62,78.55 v1(34.09,78.55)
N37838367: length 1.6
  TOP w0.305: C539.1 25.26,71.01 26,71.75 M1.A10
N37838374: length 1.8
  TOP w0.305: C540.1 26,86.55 M1.V10
N37838412: length 4
  TOP w0.102: R181.2 20.22,79.28 20.4,79.1 21.84,79.1 21.97,78.97 23.18,78.97 M1.J13
N37848751: length 15.7
  L3 w0.762: v1(33.66,43.67) 33.66,43.08 34.84,41.9 v1(34.84,31.87)
  BOTTOM w0.406: v1(34.84,31.87) 34.88,31.82 C857.1 R251.1 ; C856.1 C855.1 32.92,43.67 v1(33.66,43.67)
N37848802: length 16.2
  L3 w0.508: v1(33.76,41.92) 33.07,41.23 33.07,39.38 34,38.45 34,30.03 v1(34.65,29.38)
  BOTTOM w0.406: R250.1 C851.1 C852.1 34.88,29.15 v1(34.65,29.38)
N37855686: length 2
  TOP w0.3: U3.F11 v1(32.92,45.21)
  BOTTOM w0.406: C862.1 33.09,45.21 v1(32.92,45.21) 32.36,45.21 R259.2
N37857234: length 1.6
  BOTTOM w0.127: U36.3 R479.1
N37857254: length 1.8
  BOTTOM w0.127: R481.1 15.73,14.12 U36.7
N37859198: length 18.6
  TOP w0.102: U3.A6 27.42,40.7 26.87,40.15 26.87,33.41 25.72,32.25 25.72,27.69 24.58,26.55 R617.2 R618.2
N37859508: length 2.5
  BOTTOM w0.102: Q30.1 28.13,28.87 R602.2 28.69,29.58 R603.2
N37859577: length 3.3
  TOP w0.102: U3.AD9 v1(47.06,42.77)
  BOTTOM w0.102: R606.1 46.65,40.71 46.65,42.35 47.06,42.76 v1(47.06,42.77)
N37859659: length 5
  BOTTOM w0.102: Q25.1 27.68,24.39 27.98,24.69 28.83,24.69 29.08,24.94 Q30.3 R601.1
N37865747: length 4.1
  BOTTOM w0.305: U37.1 15.82,33.76 C899.1 16.08,32.77 R688.1 R679.2 R687.2
N37866050: length 15
  TOP w0.406: Q54.4 9.86,52.51 v2(9.83,52.48)
  BOTTOM w0.635: R701.2 10.97,46.21 9.03,48.15 9.03,51.68 v2(9.83,52.48)
N37866054: length 42.7
  L3 w0.406: v1(15.02,29.19) 15.02,35.58 v1(15.78,36.34)
  BOTTOM w0.305: U37.12 13.49,36.92
  BOTTOM w0.406: v1(15.84,50.68) 15.84,47.97 16.82,46.99 C894.1 v1(15.78,36.34) ; R695.2 v1(15.02,29.19)
  BOTTOM w0.508: 13.49,36.92 14.05,37.48
  BOTTOM w0.635: 14.05,37.48 14.05,45.19 10.46,48.77 10.46,50.92 11.24,51.69 v2(12.62,51.69)
N37866151: length 12.9
  TOP w0.406: Q44.4 11.34,50.53 v2(11.79,50.08)
  BOTTOM w0.635: R698.2 15.42,46.44 v2(11.79,50.08)
N37866161: length 53.9
  L3 w0.305: v1(22.09,9.04) 21.63,9.49 19.06,9.49 v1(18.5,8.93)
  BOTTOM w0.305: R703.1 9.88,30.43 R702.2 ; R703.1 10.65,30.9 11.26,31.51 12.24,31.51 12.49,31.76 U37.5 ; R703.1 10.93,30.43 11.21,30.14 11.21,24.55 12.01,23.75 12.01,14.19 13.74,12.47 13.74,10.86 16,8.59 18.16,8.59 v1(18.5,8.93) ; R42.2 R38.2 32.57,17.74 32.26,17.43 32.26,12.53 29.22,9.49 22.54,9.49 v1(22.09,9.04)
N37866183: length 1.5
  BOTTOM w0.305: 15.37,35.26 U37.14
  BOTTOM w0.406: R691.1 15.37,35.26
N37866191: length 2.7
  BOTTOM w0.406: C894.2 17.76,36.34 R691.2 18.54,35.26 18.66,35.14 D12.N
N37866234: length 2.8
  BOTTOM w0.305: U37.6 9.98,32.74 R700.2 R697.2
N37866247: length 3
  BOTTOM w0.305: U37.4 C910.2 11.99,30.71 R696.1
N37866267: length 2.4
  BOTTOM w0.305: U37.2 13.99,32.33 14.26,32.05
  BOTTOM w0.406: 14.26,32.05 15.02,31.3 R695.1
N37866286: length 1.9
  BOTTOM w0.305: R699.1 12.97,37.72 12.87,37.62 12.87,36.87 12.99,36.75 U37.11
N37869610: length 1.8
  BOTTOM w0.203: R742.1 R739.2 65.49,46.5 R743.1
N37869740: length 272.6
  TOP w0.305: Q76.3 73.47,76.73 73.73,76.47 C931.1 ; Q71.1 53.65,52.89 56.1,55.34 61.75,55.34 62.84,56.43 Q75.1 62.84,57.06 63.16,57.38 64.08,57.38 64.69,57.99 64.69,59.77 65.51,60.58 65.51,63.39 69,66.88 72.56,66.88 74.4,68.73 74.4,74.99 73.73,75.66 C931.1 ; v1(72.43,43.21) 72.47,43.25 Q70.1 ; C931.1 73.72,75.89 R755.1 72.9,76.18 v1(72.56,76.52) ; Q72.1 v1(11.54,86.54)
  L3 w0.254: 14.27,22.52 13.14,23.65 13.14,26.02 13.5,26.37 13.5,30.85 14.27,31.63 14.27,67.37 12.36,69.28 12.36,74.87 11.54,75.68 v1(11.54,86.54)
  L3 w0.305: v1(72.56,76.52) 72.56,73.12 69.74,70.3 69.74,69.51 70.23,69.02 71.89,69.02 73.38,67.53 73.38,65.45 71.66,63.73 71.66,62.39 73.06,60.99 73.06,44.06 72.43,43.43 v1(72.43,43.21) 72.22,43.01 72.22,22.17 65.72,15.66 65.72,9.99 62.69,6.95 60.19,6.95 59.64,6.41 58.81,6.41 57.84,7.38 48.44,7.38 47.14,6.09 41.77,6.09 40.87,6.99 18.4,6.99 14.53,10.86 14.53,12.79 15.41,13.67 15.41,21.39 14.27,22.52
  L6 w0.305: v1(66.33,76.31) 72.34,76.31 v1(72.56,76.52)
  BOTTOM w0.305: Q55.1 59.42,67.33 63.12,71.02 63.89,71.02 66.62,73.75 66.62,76.02 v1(66.33,76.31)
N37869742: length 2.2
  BOTTOM w0.305: Q55.3 60.93,64.38 61.57,63.75 R750.2
N37869760: length 1.4
  TOP w0.305: R751.2 Q70.3
N37869825: length 4.5
  BOTTOM w0.203: U39.3 62.59,53.05 62.89,52.75 62.89,50.98 62.48,50.58 C918.1 R736.1
N37869827: length 1.3
  TOP w0.406: R752.2 Q71.3
N37869857: length 1
  BOTTOM w0.254: U39.6 59.58,53.05 C914.2
N37869898: length 1.5
  BOTTOM w0.305: U41.4 U43.1
N37869909: length 2.2
  TOP w0.305: R754.2 62.75,58.76 62.92,58.59 Q75.3
N37869942: length 1.4
  TOP w0.254: R753.2 Q72.3
N37869983: length 1
  BOTTOM w0.203: U38.6 C913.2
N37870019: length 2.3
  TOP w0.102: U40.10 70.28,70.53 C922.1 71.69,69.91 R745.2
N37870110: length 4.2
  TOP w0.305: R748.1 71.97,72.29 R746.2 C926.2 71.28,74.54 70.87,74.13 U40.1
N37870179: length 1.2
  BOTTOM w0.305: U46.4 R757.1
N37870204: length 2.8
  BOTTOM w0.254: R734.2 R737.1 C917.1 67.06,63.18 U38.3
N37870231: length 2.4
  TOP w0.305: R747.2 C929.1 69.78,74.99 U40.2
N377081311: length 1.5
  BOTTOM w0.305: GQ2.1 GD10.N
N377081313: length 0.9
  BOTTOM w0.305: GR429.1 GC316.1
N377124615: length 6
  TOP w0.102: GR13.1 36.06,6.03 38.05,4.04 GCN1.48
N377124828: length 10.2
  TOP w0.508: GCN1.2 59.65,2.58 60.21,3.14 60.21,5.12 v1(60.96,5.87)
  BOTTOM w0.762: GR2.2 64.38,6.42 63.69,5.73 61.1,5.73 v1(60.96,5.87)
N377124914: length 4.9
  TOP w0.102: GR8.1 50.05,6.29 GCN1.18
N377124971: length 5
  BOTTOM w0.102: GCN1.7 57.65,4.08 57.12,4.61 GR5.1
N377125005: length 5.5
  TOP w0.102: GR11.1 45.77,5.81 47.03,4.55 47.03,3.03 46.85,2.85 GCN1.26
N377128729: length 1.6
  TOP w0.305: C1.1 58.4,72 M2.V10
N377128738: length 9.8
  TOP w0.305: M2.J10 57.94,78.25 v1(57.51,78.25)
  L3 w0.305: v1(56.03,85.96) 56.43,85.57 56.44,85.57 56.44,82.35 57.1,81.69 57.1,78.66 v1(57.51,78.25)
  BOTTOM w0.305: R5.2 v1(56.03,85.96)
N377128750: length 2.8
  TOP w0.102: M2.J13 61.05,78.15 63.11,78.15 R4.2
N377128755: length 2.2
  TOP w0.305: M2.J1 v1(50.45,78.56)
  BOTTOM w0.102: R1.1 49.32,77.72 50.16,78.56 v1(50.45,78.56)
N377131759: length 1.6
  BOTTOM w0.305: C4.1 25.67,71.03 25.67,71.83 M3.V10
N377131768: length 10.4
  L3 w0.305: v1(27.08,78.09) 27.08,78.1 27.67,78.69 27.67,85.24 v1(28.47,86.03)
  BOTTOM w0.102: v1(27.08,78.09) 27.01,78.15 26.4,78.15 M3.J10
  BOTTOM w0.305: R10.2 v1(28.47,86.03)
N377131780: length 2.7
  BOTTOM w0.102: R9.2 21.36,78.97 23.18,78.97 M3.J13
N377131785: length 1.9
  BOTTOM w0.127: R6.1 34.74,78.97 33.87,78.97 33.45,78.56 M3.J1
N377139840: length 1.6
  TOP w0.102: C8.1 R13.2 R14.1
N377139974: length 9.2
  L3 w0.305: v1(56.9,85.98) 56.97,85.91 56.97,82.59 58.15,81.41 58.15,79.1 57.85,78.8 v1(57.7,78.8)
  BOTTOM w0.305: M4.J10 58.01,78.8 v1(57.7,78.8) ; R19.2 v1(56.9,85.98)
N377139977: length 2.7
  BOTTOM w0.102: R7.2 49.67,78.53 50.11,78.97 50.63,78.97 M4.J1
N377139998: length 2
  BOTTOM w0.305: M4.A10 58.65,71.75 58.65,70.63 C5.1
N377140043: length 2.8
  BOTTOM w0.102: R18.2 63.01,78.13 61.07,78.13 M4.J13
N377218676: length 7.4
  TOP w0.305: U3.AA15 v1(45.46,47.72) ; v1(45.48,46.91) 45.44,46.91 U3.AA14
  BOTTOM w0.305: 46.28,46.88 45.55,46.88 45.52,46.91 v1(45.48,46.91) 45.48,46.96 45.46,46.98 v1(45.46,47.72)
  BOTTOM w0.406: C10.1 49.65,46.51 46.65,46.51 46.28,46.88
N377219078: length 2.7
  TOP w0.102: U3.AE22 v1(48.69,54.32)
  BOTTOM w0.102: v1(48.69,54.32) 49.2,53.8 49.92,53.8 R12.2
N377219165: length 2.8
  TOP w0.102: U3.F6 v1(32.12,40.26)
  BOTTOM w0.102: v1(32.12,40.26) 31.69,39.82 31.69,39.17 32.13,38.73 R15.1
N377220187: length 3.4
  TOP w0.305: U1.2 67.72,81.07 R23.2 67.78,80.85 R21.1
N377220223: length 1.7
  TOP w0.305: R17.1 U1.8
N377220249: length 1.7
  TOP w0.305: U1.7 R16.2
N377223530: length 4.5
  TOP w0.203: Q1.1 35.11,25.56 34.16,24.61 Q1.3 R24.2
N377223586: length 2.3
  TOP w0.203: R25.1 C19.2 30.14,24.94 U2.3
N377223596: length 2
  TOP w0.203: R25.2 32.73,25.14 33.21,25.62 Q1.2
N377223598: length 2.3
  TOP w0.203: U2.2 30.25,24.29 C19.1 R24.1
N377223616: length 1.4
  TOP w0.203: R26.2 U2.6
N377254854: length 5.3
  BOTTOM w0.203: GU1.9 66.46,38.61 GC2.2 67,37.38 67.34,37.04 67.89,37.04 68.38,37.53 68.72,37.53 GR1.1
N377255891: length 6.3
  BOTTOM w0.203: R651.2 66.54,44.75 66.54,43.25 C888.1 66.03,41.66 65.61,41.24 64.52,41.24 64.11,40.83 GU1.5
N377256292: length 7.2
  BOTTOM w0.203: R656.2 69.16,42.32 R654.1
  BOTTOM w0.305: R655.2 70.28,41.2 R654.1 69.19,43.52 R656.2 69.16,44.54 C890.1
N377256298: length 1.1
  BOTTOM w0.203: R657.2 67.69,40.19 R658.1
N377257492: length 6.2
  BOTTOM w0.203: GU1.12 65.7,37.11 66.88,35.93 R664.1 C891.1
N377258862: length 1.1
  TOP w0.406: C889.2 74.18,20.16 R661.2
N377263043: length 5.8
  BOTTOM w0.203: GC3.2 GR3.2 64.12,31.9 63.73,32.29 63.73,35.77 63.61,35.89 GU1.15
N377264652: length 1.6
  BOTTOM w0.203: GU1.14 64.11,35.9 64.38,35.62 GR4.2
N377264674: length 3.3
  BOTTOM w0.203: GU1.13 65.49,36.36 66.29,35.56 GR9.1 66.07,35.03 GR6.2
N377286625: length 0.8
  TOP w0.102: R29.1 C20.2
N377300898: length 2.8
  TOP w0.152: C24.2 47.88,35.6 47.88,36.99 48.28,37.39 U3.AE2

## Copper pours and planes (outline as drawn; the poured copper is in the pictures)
+V1P8S on TOP (solid shape): 74.46,84.21 74.46,81.9 74.12,81.55 69.1,81.55 68.55,82.1 68.55,84.07 68.68,84.19 71.09,84.19 71.23,84.33 74.33,84.33
+V1P8S on BOTTOM (solid shape): outline of 148 points within 63.68,64.89 75.47,83.13
+V3.3S on TOP (solid shape): 73.23,91.79 73.23,89.96 73.09,89.82 70.82,89.82 70.6,90.04 70.6,91.72 71.08,92.21 72.81,92.21
+V3.3S on BOTTOM (solid shape): outline of 190 points within 62.23,64.9 73.06,92.3
+V3.3S on L6 (solid shape): 73.91,90.73 73.91,87.06 73.91,86.98 73.91,86.89 73.91,84.59 75.56,82.94 75.56,80.13 74.45,79.01 74.45,75.51 74.4,75.33 74.45,75.14 74.45,72.89 75.56,71.77 75.56,61.85 75.26,61.55 74.87,61.55 74.52,61.89 74.52,70.63 73.06,72.09 73.06,79.39 74.24,80.57 74.24,82.49 72.05,84.68 72.05,89.96 70.9,91.1 70.9,91.78 71.09,91.97 72.68,91.97
+V5S on TOP (solid shape): 69.43,79.62 69.43,78.02 69.23,77.82 67.96,77.82 67.79,77.98 67.79,79.57 68.02,79.8 69.25,79.8
+V5S on TOP (solid shape): 59.69,5.48 59.69,4.77 59.36,4.44 59,4.44 57.73,3.17 57.73,2.86 57.49,2.62 57.2,2.62 57.01,2.81 57.01,4.35 58.33,5.67 59.5,5.67
GND on TOP (solid shape): 13.74,15.32 13.74,10.69 12.73,9.67 9.69,9.67 8.79,10.57 8.79,15.46 9.56,16.24 12.83,16.24
GND on TOP (solid shape): 42.06,74.53 42.06,72.57 41.86,72.37 40.14,72.37 40.08,72.43 40.08,74.54 40.16,74.62 41.97,74.62
GND on TOP (solid shape): 42.3,84.1 42.3,81.9 42.19,81.78 40.6,81.78 40.46,81.92 40.46,84.14 40.53,84.21 42.2,84.21
GND on TOP (solid shape): 57.63,65.04 57.63,63.71 57.39,63.47 54.52,63.47 54.39,63.59 54.39,64.98 54.69,65.27 57.4,65.27
GND on TOP (solid shape): 60.87,24.64 60.87,21.41 59.51,20.05 56.65,20.05 56.15,20.55 56.15,24.43 56.79,25.08 60.44,25.08
GND on TOP (solid shape): 75.12,87.58 75.12,86.72 74.82,86.42 73.06,86.42 72.96,86.52 72.96,87.67 73.09,87.8 74.9,87.8
GND on TOP (solid shape): 44.97,25.18 44.97,24.16 44.58,23.77 36.37,23.77 36.09,24.05 36.09,25.35 36.32,25.58 44.56,25.58
GND on TOP (solid shape): 66.54,75.33 66.54,73.47 66.46,73.39 65.11,73.39 64.97,73.53 64.97,75.49 65.25,75.77 66.09,75.77
GND on TOP (solid shape): 10.05,44.09 10.05,40.01 9.75,39.72 8.14,39.72 7.91,39.95 7.91,43.99 8.14,44.21 9.92,44.21
GND on TOP (solid shape): 11.3,56.53 11.3,53.59 11.09,53.37 8.19,53.37 8.01,53.55 8.01,56.47 8.23,56.69 11.15,56.69
GND on TOP (solid shape): 18.36,79.34 18.36,76.38 18.11,76.13 16.64,76.13 16.37,76.4 16.37,80.32 16.43,80.38 17.32,80.38
GND on TOP (solid shape): 49.2,31.98 49.2,28.21 48.81,27.82 47.13,27.82 46.91,28.03 46.91,32.34 47.08,32.5 48.68,32.5
GND on TOP (solid shape): 25.98,65.16 25.98,57.9 25.64,57.56 24.42,57.56 23.93,58.06 23.93,65.4 24.16,65.63 24.16,65.64 25.5,65.64
GND on TOP (solid shape): 68.34,77.18 68.34,76.1 68.68,75.76 68.68,75.01 68.92,74.77 68.92,73.82 68.82,73.72 66.84,73.72 66.71,73.84 66.71,77.34 66.93,77.55 67.97,77.55
GND on TOP (solid shape): 75.37,18.04 75.37,7.98 74.78,7.38 71.75,7.38 71.44,7.7 71.44,14.03 71.59,14.18 72.83,14.18 73.14,14.48 73.14,18.24 73.27,18.37 75.04,18.37
GND on TOP (solid shape): 67.09,61.79 67.09,57.82 66.86,57.58 65.73,57.58 65.04,58.27 65.04,59.53 65.94,60.43 65.94,61.7 66.09,61.85 67.03,61.85
GND on TOP (solid shape): 72.17,29.56 73.28,29.56 73.94,28.9 73.94,27.54 73.83,27.42 70.75,27.42 70.61,27.56 70.61,28.33 70.32,28.62 67.96,28.62 67.74,28.83 67.74,30.99 67.97,31.22 70.51,31.22
GND on TOP (solid shape): 72.75,66.24 72.75,64.29 72.59,64.14 67.95,64.14 67.73,64.36 67.73,65.12 67.87,65.26 69.08,65.26 70.38,66.57 72.42,66.57
GND on TOP (solid shape): 72.56,49.68 72.56,48.78 72.26,48.48 71.17,48.48 70.55,47.86 70.55,45.83 70.32,45.6 68.36,45.6 67.94,46.02 67.94,49.16 68.52,49.73 72.51,49.73
GND on TOP (solid shape): 74.57,41.43 74.57,32.4 74.24,32.07 70.18,32.07 69.96,32.29 69.96,40.06 69.99,40.19 69.96,40.32 69.96,42.04 70.13,42.21 73.8,42.21
GND on TOP (solid shape): 75.34,86 75.34,84.79 75.17,84.63 71.27,84.63 71.03,84.87 71.03,85.78 71.21,85.96 74.42,85.96 74.61,86.14 75.19,86.14
GND on TOP (solid shape): 61.73,54.32 61.73,51.5 61.13,50.89 59.49,50.89 59.28,50.96 59.08,50.89 57.24,50.89 56.43,51.71 56.43,54.53 56.58,54.68 61.38,54.68
GND on TOP (solid shape): 60.01,57.21 60.3,57.08 60.59,57.21 61.47,57.21 61.65,57.03 61.65,56.17 61.31,55.84 55.49,55.84 55.24,56.08 55.24,56.98 55.47,57.21
GND on TOP (solid shape): 11.73,73.56 11.73,70.99 11.67,70.89 11.56,70.92 10.89,70.68 11.56,70.44 11.67,70.47 11.73,70.37 11.73,68.19 10.93,67.39 8.41,67.39 7.85,67.95 7.85,73.25 8.39,73.79 11.51,73.79
GND on TOP (solid shape): outline of 683 points within 7.01,3.61 76.19,97.79
GND on BOTTOM (solid shape): 18.97,64.33 18.97,61.84 18.85,61.71 16.57,61.71 16.47,61.82 16.47,64.37 16.59,64.48 18.82,64.48
GND on BOTTOM (solid shape): 19.02,58.07 19.02,55.62 18.87,55.47 16.57,55.47 16.42,55.62 16.42,58.08 16.55,58.21 18.88,58.21
GND on BOTTOM (solid shape): 42.11,74.58 42.11,72.43 42,72.32 40.28,72.32 40.2,72.41 40.2,74.57 40.31,74.68 42.01,74.68
GND on BOTTOM (solid shape): 42.32,84.17 42.32,81.91 42.21,81.81 40.55,81.81 40.43,81.93 40.43,84.12 40.56,84.26 42.24,84.26
GND on BOTTOM (solid shape): 62.45,59.49 62.45,58.06 62.36,57.97 61.46,57.97 61.01,58.41 61.01,59.29 61.39,59.67 62.27,59.67
GND on BOTTOM (solid shape): 48.48,33.88 48.48,26.14 47.79,25.46 46.58,25.46 46.42,25.62 46.42,31.64 46.72,31.94 46.72,33.92 46.89,34.09 48.26,34.09
GND on BOTTOM (solid shape): 53.19,53.92 53.19,53.27 52.83,52.91 51.02,52.91 50.81,53.12 50.81,53.98 51.02,54.18 52.92,54.18
GND on BOTTOM (solid shape): 66.68,66.29 66.68,65.05 66.57,64.95 65.56,64.95 65.46,65.05 65.46,66.31 65.62,66.48 66.48,66.48
GND on BOTTOM (solid shape): 56.2,62.92 56.2,60.98 55.9,60.68 55.26,60.68 55.08,60.68 50.07,60.68 50,60.75 50,62.7 50.3,63 56.12,63
GND on BOTTOM (solid shape): 70.64,49.66 70.64,46.07 70.14,45.57 68.44,45.57 68.02,45.99 68.02,48.37 67.4,48.99 67.4,49.69 67.5,49.79 70.51,49.79
GND on BOTTOM (solid shape): 59.68,64.51 59.68,63.78 59.99,63.47 60.52,63.47 60.82,63.16 60.82,62.45 60.68,62.31 58.41,62.31 58.05,62.67 58.05,64.55 58.33,64.83 59.36,64.83
GND on BOTTOM (solid shape): 62.03,23.74 62.03,22.8 61.35,22.12 61.35,19.4 60.9,18.94 57.43,18.94 56.62,19.75 56.62,21.71 57.05,22.14 57.05,23.59 57.3,23.84 61.93,23.84
GND on BOTTOM (solid shape): 70.92,30.89 70.92,28.89 70.68,28.64 69.09,28.64 68.78,28.34 68.78,27.4 68.73,27.35 65.72,27.35 65.47,27.6 65.47,29.14 67.41,31.08 70.73,31.08
GND on BOTTOM (solid shape): 40.18,45.95 40.26,45.95 40.32,45.89 40.32,45.04 40.26,44.98 40.26,44.71 40.09,44.53 39.57,44.53 38.91,45.2 38.83,45.27 38.56,45.27 38.48,45.35 38.48,45.82 38.66,45.99 40.14,45.99
GND on BOTTOM (solid shape): 52.74,56.95 52.74,55.66 52.57,55.48 51.49,55.48 51.3,55.67 50.47,55.67 50.43,55.71 50.43,56.24 50.47,56.28 51.18,56.28 51.32,56.42 51.32,57.1 51.4,57.18 52.51,57.18
GND on BOTTOM (solid shape): 53.51,49.85 56.16,49.85 56.32,49.69 56.34,49.69 56.34,48.42 56.22,48.3 52.37,48.3 52.02,47.95 49.25,47.95 48.56,47.26 48.56,47.08 48.41,46.93 47.66,46.93 47.54,47.05 47.54,47.72 47.55,47.72 47.55,47.76 47.68,47.88 47.68,49.48 47.75,49.55 47.76,49.54 48.9,49.54 49.19,49.83 49.19,50.29 49.38,50.48 52.88,50.48
